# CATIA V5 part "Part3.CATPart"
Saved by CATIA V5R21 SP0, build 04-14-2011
Part number: Part3
Bounding box of the stored display mesh (mm): x 0 to 0, y -138.815 to 139, z -138.812 to 138.81
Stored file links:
  C:\Users\RIAD MAHAMUD PIASH\Desktop\Part3.CATPart
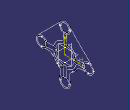
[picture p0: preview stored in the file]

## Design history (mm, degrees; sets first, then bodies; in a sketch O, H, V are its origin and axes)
Body1 (main body)
  Sketch1 on yz-plane, origin (0, 0, 0), H (0, 1, 0), V (0, 0, 1)
    circle A1 centre (113, 0) radius 26
    point P1 (113, 0)
    arc A2 centre (-113, 0) radius 26 from (-89, -10) to (-89, 10) cw
    arc A3 centre (0, -113) radius 26 from (-23.1515, -101.1676) to (23.1515, -101.1676) ccw
    point P3 (0, -113)
    circle A4 centre (0, 113) radius 26
    circle A5 centre (0, 0) radius 44
    arc A6 centre (0, 0) radius 55 from (-54.0833, -10) to (-10, -54.0833) ccw
    arc A7 centre (0, 0) radius 64 from (-52.6806, -36.3421) to (-36.7893, -52.3693) ccw
    circle A8 centre (0, 113) radius 20
    circle A9 centre (-113, 0) radius 20
    circle A10 centre (0, -113) radius 20
    circle A11 centre (113, 0) radius 20
    point P8 (-44, 0)
    line L1 (-42.8486, 10) -> (-95.6795, 10)
    point P9 (-42.8486, 10)
    line L2 (-42.8486, -10) -> (-95.6795, -10)
    point P11 (-95.6795, 10)
    point P12 (-95.6795, -10)
    point P13 (-89, -10)
    point P14 (-89, 10)
    point P15 (-54.0833, 10)
    point P16 (-54.0833, -10)
    line L3 (10, -42.8486) -> (10, -95.6795)
    line L4 (-10, -42.8486) -> (-10, -95.6795)
    line L5 (42.8486, 10) -> (95.6795, 10)
    line L6 (42.8486, -10) -> (95.6795, -10)
    line L7 (-10, 42.8486) -> (-10, 95.6795)
    line L8 (10, 42.8486) -> (10, 95.6795)
    line L9 (-21.1535, 128.616) -> (-131.7496, 18.0199)
    point P29 (-21.1535, 128.616)
    point P30 (-131.7496, 18.0199)
    point P31 (131.7496, 18.0199)
    point P32 (21.1535, 128.616)
    line L10 (21.1535, 128.616) -> (131.7496, 18.0199)
    point P33 (-101.9286, -23.525)
    arc A12 centre (-85.0783, -59.8026) radius 40 from (-101.9286, -23.525) to (-52.0335, -37.2628) cw
    point P35 (-52.0335, -37.2628)
    point P36 (-23.9394, -102.8557)
    arc A13 centre (-59.7826, -85.1002) radius 40 from (-23.9394, -102.8557) to (-36.7893, -52.3693) ccw
    point P38 (-36.7893, -52.3693)
    point P39 (52.0335, -37.2628)
    point P40 (101.9286, -23.525)
    arc A14 centre (85.0783, -59.8026) radius 40 from (101.9286, -23.525) to (52.0335, -37.2628) ccw
    point P42 (36.7893, -52.3693)
    point P43 (23.9394, -102.8557)
    arc A15 centre (59.7826, -85.1002) radius 40 from (23.9394, -102.8557) to (36.7893, -52.3693) cw
    point P45 (-23.1515, -101.1676)
    point P46 (23.1515, -101.1676)
    point P47 (52.6806, -36.3421)
    point P48 (-52.6806, -36.3421)
    arc A16 centre (0, 0) radius 64 from (36.7893, -52.3693) to (52.6806, -36.3421) ccw
    point P49 (-10, -54.0833)
    arc A17 centre (0, 0) radius 55 from (10, -54.0833) to (54.0833, -10) ccw
    point P50 (10, -54.0833)
    point P51 (10, 54.0833)
    arc A18 centre (0, 0) radius 55 from (-10, 54.0833) to (-54.0833, 10) ccw
    point P52 (-10, 54.0833)
    point P53 (54.0833, -10)
    arc A19 centre (0, 0) radius 55 from (54.0833, 10) to (10, 54.0833) ccw
    point P54 (54.0833, 10)
    radius A1 = 26
    distance P1 V = 113
    radius A3 = 26
    distance P3 H = 113
    radius A5 = 44
    radius A6 = 55
    radius A7 = 64
    radius A8 = 20
    radius A12 = 40
    radius A13 = 40
    coincidence: P1 H, P3 V, P8 A5, P8 H, P9 A5, A9 P11, A9 P12, L2 P13, L1 P14, L1 P15, L2 P16, P33 A2, P35 A7, P36 A3, A13 P45, A15 P46, A14 P47, A12 P48, A7 A16, L4 P49, L3 P50, A6 A17, L8 P51, L7 P52, A17 A18, L6 P53, L5 P54, A17 A19
    symmetry: A1 A2 V, A3 A4 H, P30 P31 V, P29 P32 V, L9 L10 V, P35 P39 V, P33 P40 V, A12 A14 V, P38 P42 V, P36 P43 V, A13 A15 V
    horizontal: L1 H
    tangency: L9 A4, L9 A2, A13 A7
